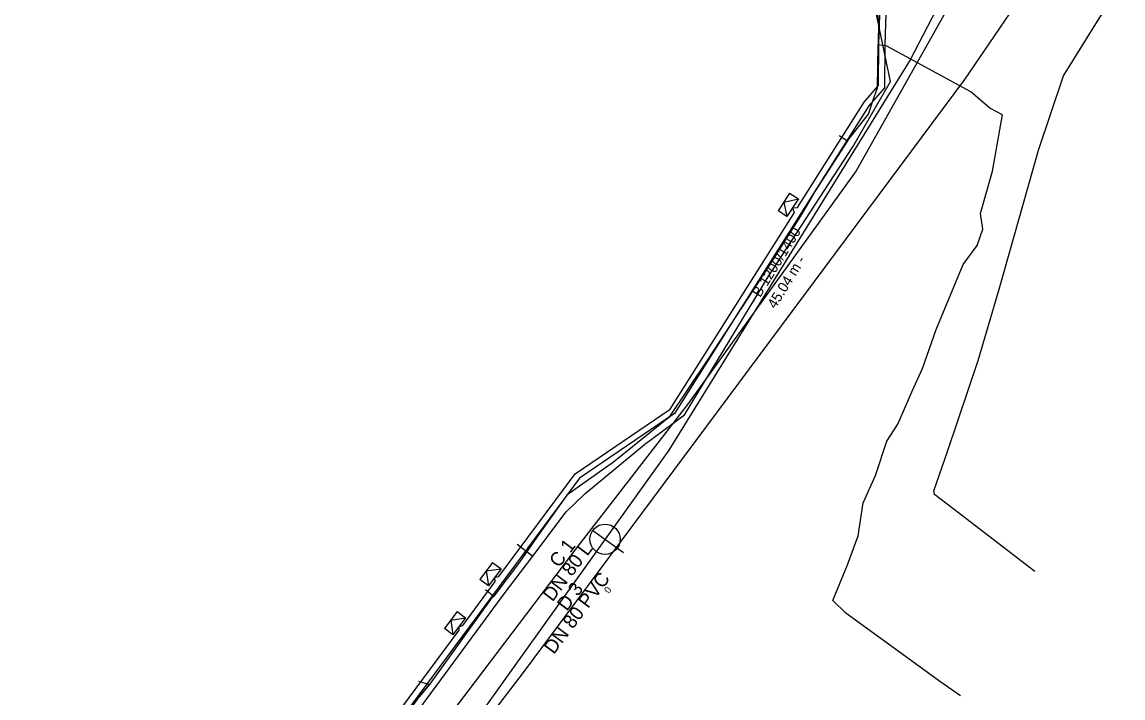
# Model space of a CAD drawing. Extents: x -600636 to -600148, y -1203980 to -1203569.
# Drawn here: x -600302.2 to -600229.4, y -1203773.6 to -1203728.9 of the extents above; entities that cross this region are included whole.
import ezdxf

# ---------------------------------------------------------------- set-up
doc = ezdxf.new("R2010")
doc.units = 0
for name, color, linetype in [('Cetin zam průběh', 7, 'Continuous'), ('EON podzemní NN', 7, 'Continuous'), ('GasNet NTL', 7, 'Continuous'), ('Implicitní', 7, 'Continuous'), ('VaK Břeclav_kanalizace', 7, 'Continuous'), ('VaK Břeclav_kanalizace_popis', 7, 'Continuous'), ('Vak Břeclav_vodovod', 7, 'Continuous'), ('Vak Břeclav_vodovod_popis', 7, 'Continuous'), ('Vrstva 9', 7, 'Continuous')]:
    doc.layers.add(name, color=color, linetype=linetype)

# ---------------------------------------------------------------- blocks, each defined once
blk = doc.blocks.new('NN630')
at = {"layer": 'Vrstva 9'}
for points in [[(-0.003, -0.7), (-0.703, 0)], [(-0.703, -0.7), (-0.703, 0), (0.697, 0), (0.697, -0.7)], [(-0.703, -0.7), (0.697, -0.7)], [(-0.003, -0.7), (0.697, 0)]]:
    blk.add_lwpolyline(points, dxfattribs=at)
blk = doc.blocks.new('MoSymbol 2')
at = {"layer": 'Implicitní'}
blk.add_line((0, 0.0005), (0, -0.00075), dxfattribs=at)
blk.add_circle((0, 0), 0.0005, dxfattribs=at)

msp = doc.modelspace()

# ---------------------------------------------------------------- linework, layer by layer
at = {"layer": 'Cetin zam průběh'}
for points in [[(-600235.23, -1203765.23), (-600240.65, -1203761.08), (-600241.86, -1203760.15), (-600241.91, -1203759.91), (-600241.01, -1203757.3), (-600238.98, -1203751.29), (-600237.59, -1203746.58), (-600234.99, -1203737.4), (-600233.35, -1203732.5), (-600229.76, -1203726.69), (-600229.41, -1203725.62), (-600238.73, -1203718.32)], [(-600247.46, -1203726.17), (-600246.45, -1203726.91), (-600245.74, -1203727.75), (-600245.58, -1203728.9), (-600245.6, -1203730.45)], [(-600247.63, -1203736.78), (-600246.24, -1203735.03), (-600245.92, -1203734.07), (-600245.64, -1203733.29), (-600245.6, -1203730.45)], [(-600239.05, -1203743.7), (-600238.67, -1203742.61), (-600238.83, -1203741.58), (-600238.03, -1203738.79), (-600237.38, -1203735.06), (-600238.22, -1203734.62), (-600239.47, -1203733.54), (-600245.01, -1203730.52), (-600245.6, -1203730.45)], [(-600239.47, -1203733.54), (-600245.01, -1203730.52)], [(-600247.63, -1203736.78), (-600249.78, -1203740.13), (-600250.65, -1203741.61), (-600252.8, -1203745.02), (-600256.84, -1203751.19), (-600259.44, -1203755.05), (-600263.1, -1203758.01), (-600266.17, -1203760.2), (-600268.16, -1203762.96), (-600269.31, -1203764.61), (-600271.01, -1203766.87)], [(-600248.17, -1203736.43), (-600247.63, -1203736.78)], [(-600250.65, -1203741.61), (-600252.8, -1203745.02)], [(-600240.15, -1203773.44), (-600241.45, -1203772.54), (-600247.73, -1203767.99), (-600248.59, -1203767.15), (-600247.62, -1203764.78), (-600246.91, -1203762.88), (-600246.59, -1203760.7), (-600245.78, -1203758.89), (-600245.03, -1203756.62), (-600244.3, -1203755.49), (-600243.34, -1203753.33), (-600242.67, -1203751.82), (-600241.75, -1203749.25), (-600239.98, -1203744.96), (-600239.05, -1203743.7)], [(-600263.1, -1203758.01), (-600266.17, -1203760.2)], [(-600268.16, -1203762.96), (-600269.31, -1203764.61)], [(-600271.55, -1203766.42), (-600271.01, -1203766.87)], [(-600271.01, -1203766.87), (-600271.21, -1203767.09), (-600275.25, -1203772.7)], [(-600271.21, -1203767.09), (-600275.25, -1203772.7)], [(-600241.45, -1203772.54), (-600247.73, -1203767.99)], [(-600275.98, -1203772.47), (-600275.25, -1203772.7)], [(-600277, -1203775.03), (-600275.93, -1203773.51), (-600275.25, -1203772.7)], [(-600275.25, -1203772.7), (-600275.93, -1203773.51)]]:
    msp.add_lwpolyline(points, dxfattribs=at)
at = {"layer": 'EON podzemní NN'}
for points in [[(-600241.115, -1203718.296), (-600241.956, -1203719.116), (-600246.209, -1203724.801), (-600246.442, -1203725.59), (-600245.068, -1203727.725), (-600245.152, -1203730.414), (-600245.18, -1203733.274), (-600246.203, -1203734.474), (-600259.048, -1203754.786), (-600265.34, -1203759.062), (-600294.932, -1203798.94), (-600294.8, -1203799.42), (-600294.6, -1203799.71), (-600294.639, -1203800.117), (-600301.927, -1203809.794), (-600302.189, -1203809.81)], [(-600281.885, -1203780.687), (-600273.294, -1203769.109), (-600273.288, -1203768.864), (-600273.055, -1203768.788), (-600270.904, -1203765.889), (-600270.944, -1203765.611), (-600270.666, -1203765.567), (-600265.625, -1203758.774), (-600259.342, -1203754.503), (-600251.131, -1203741.518), (-600251.247, -1203741.205), (-600250.916, -1203741.179), (-600246.523, -1203734.232), (-600245.578, -1203733.124), (-600245.552, -1203730.406), (-600245.472, -1203727.837), (-600246.878, -1203725.652), (-600246.627, -1203724.801), (-600253.016, -1203720.855), (-600254.117, -1203722.507)]]:
    msp.add_lwpolyline(points, dxfattribs=at)
at = {"layer": 'GasNet NTL'}
for points in [[(-600295.95, -1203801.21), (-600295.65, -1203800.81), (-600287.36, -1203789.82), (-600286.53, -1203788.7), (-600278.7, -1203778.11), (-600278.55, -1203777.91), (-600275.98, -1203774.4), (-600270.38, -1203766.79), (-600268.42, -1203764.21), (-600266.21, -1203761.3), (-600264.99, -1203760.1), (-600261.02, -1203756.81), (-600258.4, -1203754.89), (-600252.86, -1203745.77), (-600247.26, -1203737.18), (-600244.78, -1203732.86), (-600245.17, -1203730.96), (-600245.99, -1203727.04), (-600245.48, -1203726.22)], [(-600269.45, -1203763.43), (-600268.42, -1203764.21)]]:
    msp.add_lwpolyline(points, dxfattribs=at)
at = {"layer": 'VaK Břeclav_kanalizace'}
for points in [[(-600240.031, -1203724.796), (-600243.482, -1203731.424), (-600245.022, -1203733.915), (-600249.522, -1203741.19), (-600259.43, -1203757.209), (-600263.646, -1203763.102)], [(-600263.646, -1203763.102), (-600288.953, -1203798.483), (-600301.999, -1203816.723)]]:
    msp.add_lwpolyline(points, dxfattribs=at)
at = {"layer": 'Vak Břeclav_vodovod'}
for points in [[(-600237.019, -1203720.962), (-600247.043, -1203738.764), (-600258.194, -1203754.202), (-600265.436, -1203763.558), (-600282.474, -1203785.988), (-600297.618, -1203805.864)], [(-600294.521, -1203805.29), (-600277.888, -1203783.466), (-600269.03, -1203771.912), (-600239.859, -1203732.742), (-600236.89, -1203728.365)]]:
    msp.add_lwpolyline(points, dxfattribs=at)

# ---------------------------------------------------------------- block references
at = {"layer": 'EON podzemní NN'}
for p, rotation in [((-600251.248, -1203741.205), -122.73661115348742), ((-600270.943, -1203765.611), -126.62638886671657), ((-600273.288, -1203768.864), -126.7565000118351)]:
    msp.add_blockref('NN630', p, dxfattribs=dict(at, rotation=rotation))
at = {"layer": 'VaK Břeclav_kanalizace', "xscale": 1999.750031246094, "yscale": 1999.750031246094, "rotation": 54.424444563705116}
msp.add_blockref('MoSymbol 2', (-600263.646, -1203763.102), dxfattribs=at)

# ---------------------------------------------------------------- texts
at = {"layer": 'VaK Břeclav_kanalizace_popis'}
for s, height, rotation, p in [('- B 1200/1400', 0.68241, 58.26325, (-600253.687, -1203747.641)), ('45.04 m -', 0.6824, 58.26325, (-600252.389, -1203747.922)), ('0', 0.455, 54.42444, (-600263.383, -1203766.717))]:
    msp.add_text(s, height=height, rotation=rotation, dxfattribs=at).set_placement(p)
at = {"layer": 'Vak Břeclav_vodovod_popis'}
for s, rotation, p in [('C 1', 52.77942, (-600266.69, -1203765.032)), ('DN 80 L', 52.77942, (-600267.119, -1203767.277)), ('DN 80 PVC', 53.32391, (-600267.033, -1203770.754)), ('D 3', 53.32391, (-600266.171, -1203767.897))]:
    msp.add_text(s, height=0.9099, rotation=rotation, dxfattribs=at).set_placement(p)

doc.saveas('drawing.dxf')
